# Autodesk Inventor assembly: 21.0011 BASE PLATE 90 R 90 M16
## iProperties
Created: 2009-01
Part Number: 21.0011 BASE PLATE 90 R 90 M16
Document SubType Name: Assembly
Designer: Administrator
Author: Administrator
